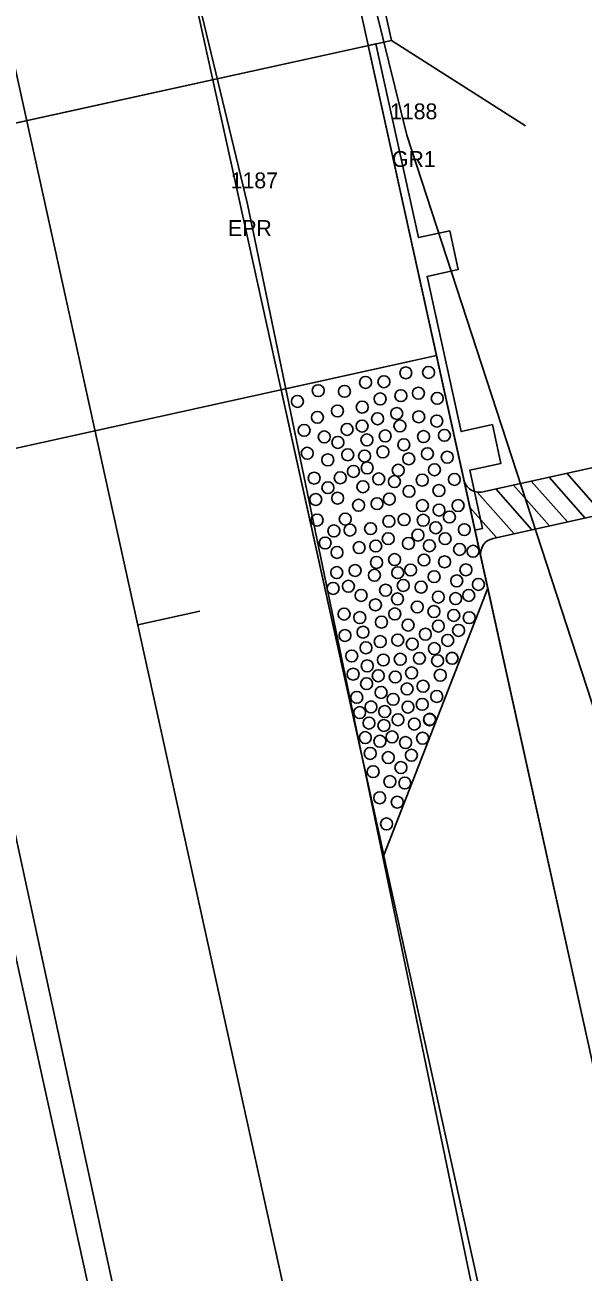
# Model space of a CAD drawing. Extents: x 2520975 to 2526538, y 881018 to 888064.
# Drawn here: x 2523803.6 to 2523838.7, y 884983.7 to 885062.2 of the extents above; entities that cross this region are included whole.
import ezdxf

# ---------------------------------------------------------------- set-up
doc = ezdxf.new("R2010")
doc.units = 0
for name, color, linetype in [('RD_EX_GuardRail', 7, 'Continuous'), ('RD_EX_GuardRail_txCode', 7, 'Continuous'), ('RD_EX_Road', 7, 'Continuous'), ('RD_EX_Road_txCode', 7, 'Continuous'), ('RD_HC_Cl', 7, 'Continuous'), ('RD_HC_Data_Tic', 7, 'Continuous'), ('RD_PD_Bridge', 7, 'Continuous'), ('RD_PD_Final_TrvlWay', 7, 'Continuous'), ('RD_PD_GR', 7, 'Continuous'), ('RD_PD_PaveShd', 7, 'Continuous'), ('RD_SMD_Locator', 7, 'Continuous')]:
    doc.layers.add(name, color=color, linetype=linetype)

# ---------------------------------------------------------------- blocks, each defined once
blk = doc.blocks.new('TBC1')
at = {"layer": 'RD_PD_GR'}
blk.add_lwpolyline([(12.5, 2.5), (15, 2.5), (15, 0.492), (25, 0.492), (25, 2.5), (27.5, 2.5), (27.5, 0.492), (31.25, 0.492), (31.25, 0), (0, 0), (0, 0.492), (12.5, 0.492)], close=True, dxfattribs=at)

msp = doc.modelspace()

# ---------------------------------------------------------------- linework, layer by layer
at = {"layer": 'RD_EX_GuardRail'}
msp.add_lwpolyline([(2523841.112, 885013.814), (2523827.604, 885055.265), (2523819.275, 885089.086)], dxfattribs=at)
at = {"layer": 'RD_EX_Road'}
for p, q in [((2523817.578, 885050.917), (2523809.375, 885084.881)), ((2523837.97, 884952.456), (2523817.578, 885050.917)), ((2523816.996, 884946.299), (2523795.465, 885045.906))]:
    msp.add_line(p, q, dxfattribs=at)
at = {"layer": 'RD_HC_Cl'}
for p, q in [((2523662.651, 885798.932), (2524219.244, 883271.288)), ((2523641.165, 885794.201), (2524197.759, 883266.557))]:
    msp.add_line(p, q, dxfattribs=at)
at = {"layer": 'RD_HC_Data_Tic'}
msp.add_line((2523810.669, 885024.44), (2523814.575, 885025.3), dxfattribs=at)
at = {"layer": 'RD_PD_Bridge'}
for p, q in [((2523780.729, 885051.128), (2523826.629, 885061.235)), ((2523826.629, 885061.235), (2523835.056, 885055.85)), ((2523825.164, 885060.913), (2523829.465, 885041.381)), ((2523829.465, 885041.381), (2523786.495, 885031.918))]:
    msp.add_line(p, q, dxfattribs=at)
for points in [[(2523826.629, 885061.235), (2523798.673, 885188.194)], [(2523780.729, 885051.128), (2523826.629, 885061.235)]]:
    msp.add_lwpolyline(points, dxfattribs=at)
at = {"layer": 'RD_PD_Final_TrvlWay'}
for p, q in [((2523720.239, 885490.907), (2524037.438, 884050.417)), ((2523696.801, 885485.745), (2524014, 884045.256))]:
    msp.add_line(p, q, dxfattribs=at)
at = {"layer": 'RD_PD_GR'}
msp.add_line((2523831.885, 885030.394), (2523990.484, 884310.149), dxfattribs=at)
at = {"layer": 'RD_PD_PaveShd'}
for p, q in [((2523819.699, 885039.23), (2523829.465, 885041.381)), ((2523829.465, 885041.381), (2523831.401, 885032.591)), ((2523819.699, 885039.23), (2523826.151, 885009.932)), ((2523854.955, 885037.791), (2523832.378, 885032.807)), ((2523833.022, 885029.877), (2523855.634, 885034.868)), ((2523836.542, 885033.726), (2523838.816, 885031.156)), ((2523837.659, 885033.973), (2523839.933, 885031.402)), ((2523837.659, 885033.973), (2523839.933, 885031.402)), ((2523833.191, 885032.986), (2523835.465, 885030.416)), ((2523833.191, 885032.986), (2523835.465, 885030.416)), ((2523834.308, 885033.233), (2523836.582, 885030.663)), ((2523834.308, 885033.233), (2523836.582, 885030.663)), ((2523835.425, 885033.48), (2523837.699, 885030.909)), ((2523835.425, 885033.48), (2523837.699, 885030.909)), ((2523831.401, 885032.591), (2523832.046, 885029.661)), ((2523832.027, 885032.793), (2523834.348, 885030.17)), ((2523831.577, 885031.792), (2523833.231, 885029.923)), ((2523832.046, 885029.661), (2523832.691, 885026.732)), ((2523826.151, 885009.932), (2523832.691, 885026.732))]:
    msp.add_line(p, q, dxfattribs=at)
for centre in [(2523824.999, 885039.698), (2523824.999, 885039.698), (2523826.153, 885039.739), (2523826.153, 885039.739), (2523827.534, 885040.3), (2523827.534, 885040.3), (2523828.967, 885040.325), (2523828.967, 885040.325), (2523828.967, 885040.325), (2523822.02, 885039.178), (2523822.02, 885039.178), (2523823.673, 885039.133), (2523823.673, 885039.133), (2523827.222, 885038.86), (2523827.222, 885038.86), (2523828.326, 885039.017), (2523828.326, 885039.017), (2523820.715, 885038.501), (2523820.715, 885038.501), (2523824.791, 885038.139), (2523824.791, 885038.139), (2523825.918, 885038.659), (2523825.918, 885038.659), (2523829.513, 885038.692), (2523829.513, 885038.692), (2523821.973, 885037.498), (2523821.973, 885037.498), (2523823.233, 885037.898), (2523823.233, 885037.898), (2523825.757, 885037.407), (2523825.757, 885037.407), (2523826.962, 885037.739), (2523826.962, 885037.739), (2523828.347, 885037.529), (2523828.347, 885037.529), (2523829.482, 885037.263), (2523829.482, 885037.263), (2523821.137, 885036.679), (2523821.137, 885036.679), (2523823.836, 885036.738), (2523823.836, 885036.738), (2523824.78, 885036.947), (2523824.78, 885036.947), (2523827.161, 885036.956), (2523827.161, 885036.956), (2523822.403, 885036.265), (2523822.403, 885036.265), (2523823.257, 885035.918), (2523823.257, 885035.918), (2523825.086, 885036.073), (2523825.086, 885036.073), (2523826.234, 885036.326), (2523826.234, 885036.326), (2523827.408, 885035.773), (2523827.408, 885035.773), (2523828.647, 885036.286), (2523828.647, 885036.286), (2523829.96, 885036.364), (2523829.96, 885036.364), (2523821.33, 885035.236), (2523821.33, 885035.236), (2523823.878, 885035.137), (2523823.878, 885035.137), (2523824.938, 885035.058), (2523826.089, 885035.32), (2523826.089, 885035.32), (2523827.719, 885034.884), (2523827.719, 885034.884), (2523828.889, 885035.205), (2523828.889, 885035.205), (2523830.139, 885034.988), (2523830.139, 885034.988), (2523822.624, 885034.82), (2523822.624, 885034.82), (2523824.24, 885034.09), (2523824.24, 885034.09), (2523825.101, 885034.315), (2523825.101, 885034.315), (2523827.057, 885034.167), (2523827.057, 885034.167), (2523829.333, 885034.196), (2523829.333, 885034.196), (2523821.767, 885033.666), (2523821.767, 885033.666), (2523823.407, 885033.689), (2523823.407, 885033.689), (2523825.83, 885033.62), (2523825.83, 885033.62), (2523826.817, 885033.452), (2523826.817, 885033.452), (2523828.563, 885033.542), (2523828.563, 885033.542), (2523830.587, 885033.586), (2523830.587, 885033.586), (2523822.633, 885033.066), (2523822.633, 885033.066), (2523824.832, 885033.125), (2523824.832, 885033.125), (2523827.734, 885032.835), (2523827.734, 885032.835), (2523829.618, 885032.888), (2523829.618, 885032.888), (2523821.864, 885032.324), (2523821.864, 885032.324), (2523823.244, 885032.408), (2523823.244, 885032.408), (2523824.564, 885031.963), (2523824.564, 885031.963), (2523825.721, 885032.06), (2523825.721, 885032.06), (2523826.497, 885032.349), (2523826.497, 885032.349), (2523828.577, 885031.941), (2523828.577, 885031.941), (2523830.823, 885031.944), (2523830.823, 885031.944), (2523821.953, 885031.028), (2523821.953, 885031.028), (2523823.725, 885031.088), (2523823.725, 885031.088), (2523826.467, 885030.948), (2523826.467, 885030.948), (2523827.428, 885031.058), (2523827.428, 885031.058), (2523828.627, 885031.016), (2523828.627, 885031.016), (2523829.621, 885031.656), (2523829.621, 885031.656), (2523830.274, 885031.22), (2523830.274, 885031.22), (2523823.006, 885030.346), (2523823.006, 885030.346), (2523824.02, 885030.397), (2523824.02, 885030.397), (2523825.316, 885030.486), (2523825.316, 885030.486), (2523829.418, 885030.543), (2523829.418, 885030.543), (2523831.214, 885030.426), (2523831.214, 885030.426), (2523822.459, 885029.586), (2523825.639, 885029.394), (2523825.639, 885029.394), (2523826.429, 885029.856), (2523826.429, 885029.856), (2523827.701, 885029.554), (2523827.701, 885029.554), (2523828.295, 885030.079), (2523828.295, 885030.079), (2523829.019, 885029.41), (2523829.019, 885029.41), (2523830.001, 885029.855), (2523830.001, 885029.855), (2523823.203, 885028.987), (2523823.203, 885028.987), (2523824.598, 885029.295), (2523824.598, 885029.295), (2523830.914, 885029.182), (2523830.914, 885029.182), (2523831.766, 885029.063), (2523831.766, 885029.063), (2523824.341, 885027.852), (2523824.341, 885027.852), (2523825.691, 885028.358), (2523825.691, 885028.358), (2523826.825, 885028.541), (2523826.825, 885028.541), (2523827.831, 885027.884), (2523827.831, 885027.884), (2523828.676, 885028.512), (2523828.676, 885028.512), (2523829.968, 885028.398), (2523829.968, 885028.398), (2523831.312, 885027.895), (2523831.312, 885027.895), (2523823.189, 885027.719), (2523823.189, 885027.719), (2523825.558, 885027.553), (2523825.558, 885027.553), (2523827.027, 885027.715), (2523827.027, 885027.715), (2523829.314, 885027.463), (2523829.314, 885027.463), (2523830.736, 885027.201), (2523830.736, 885027.201), (2523832.098, 885026.977), (2523832.098, 885026.977), (2523832.098, 885026.977), (2523822.96, 885026.723), (2523822.96, 885026.723), (2523823.922, 885026.86), (2523823.922, 885026.86), (2523824.722, 885026.285), (2523824.722, 885026.285), (2523826.258, 885026.612), (2523826.258, 885026.612), (2523827.371, 885026.909), (2523827.371, 885026.909), (2523828.495, 885026.805), (2523828.495, 885026.805), (2523831.494, 885026.285), (2523831.494, 885026.285), (2523825.619, 885025.69), (2523825.619, 885025.69), (2523827.01, 885026.061), (2523827.01, 885026.061), (2523828.25, 885025.557), (2523828.25, 885025.557), (2523829.579, 885026.177), (2523829.579, 885026.177), (2523830.668, 885026.083), (2523830.668, 885026.083), (2523823.647, 885025.109), (2523823.647, 885025.109), (2523824.637, 885024.887), (2523824.637, 885024.887), (2523826.84, 885025.117), (2523826.84, 885025.117), (2523829.299, 885025.269), (2523829.299, 885025.269), (2523830.547, 885025.024), (2523830.547, 885025.024), (2523831.521, 885024.88), (2523831.521, 885024.88), (2523824.84, 885023.97), (2523824.84, 885023.97), (2523826.002, 885024.601), (2523826.002, 885024.601), (2523827.675, 885024.414), (2523827.675, 885024.414), (2523828.762, 885023.842), (2523828.762, 885023.842), (2523829.58, 885024.354), (2523829.58, 885024.354), (2523830.854, 885024.079), (2523830.854, 885024.079), (2523823.705, 885023.759), (2523823.705, 885023.759), (2523825.92, 885023.378), (2523825.92, 885023.378), (2523827.027, 885023.472), (2523827.027, 885023.472), (2523827.938, 885023.219), (2523827.938, 885023.219), (2523830.17, 885023.448), (2523830.17, 885023.448), (2523824.131, 885022.47), (2523824.131, 885022.47), (2523825.026, 885022.984), (2523825.026, 885022.984), (2523827.181, 885022.266), (2523827.181, 885022.266), (2523828.389, 885022.322), (2523828.389, 885022.322), (2523829.325, 885022.938), (2523829.325, 885022.938), (2523830.44, 885022.322), (2523830.449, 885022.329), (2523825.102, 885021.848), (2523825.102, 885021.848), (2523826.119, 885022.219), (2523826.119, 885022.219), (2523829.53, 885022.168), (2523829.53, 885022.168), (2523824.22, 885021.325), (2523824.22, 885021.325), (2523825.063, 885020.725), (2523825.063, 885020.725), (2523825.799, 885021.225), (2523825.799, 885021.225), (2523826.869, 885021.144), (2523826.869, 885021.144), (2523827.898, 885021.404), (2523827.898, 885021.404), (2523829.699, 885021.26), (2523829.699, 885021.26), (2523825.975, 885020.172), (2523825.975, 885020.172), (2523827.612, 885020.396), (2523827.612, 885020.396), (2523828.618, 885020.568), (2523828.618, 885020.568), (2523829.483, 885019.92), (2523829.483, 885019.92), (2523824.449, 885019.865), (2523824.449, 885019.865), (2523825.343, 885019.265), (2523825.343, 885019.265), (2523826.735, 885019.741), (2523826.735, 885019.741), (2523827.668, 885019.251), (2523827.668, 885019.251), (2523828.563, 885019.424), (2523828.563, 885019.424), (2523824.631, 885018.908), (2523824.631, 885018.908), (2523826.207, 885018.972), (2523826.207, 885018.972), (2523827.041, 885018.456), (2523827.041, 885018.456), (2523829.025, 885018.456), (2523829.036, 885018.488), (2523825.216, 885018.247), (2523825.216, 885018.247), (2523826.153, 885018.093), (2523826.153, 885018.093), (2523828.067, 885018.184), (2523828.067, 885018.184), (2523824.984, 885017.331), (2523824.984, 885017.331), (2523825.9, 885017.099), (2523825.9, 885017.099), (2523826.67, 885017.372), (2523826.67, 885017.372), (2523827.515, 885017.016), (2523827.515, 885017.016), (2523828.589, 885017.293), (2523828.589, 885017.293), (2523825.292, 885016.334), (2523825.292, 885016.334), (2523826.43, 885016.072), (2523826.43, 885016.072), (2523827.885, 885016.22), (2523827.226, 885015.446), (2523827.226, 885015.446), (2523825.478, 885015.184), (2523825.478, 885015.184), (2523826.53, 885014.559), (2523826.53, 885014.559), (2523827.471, 885014.469), (2523827.471, 885014.469), (2523825.89, 885013.54), (2523825.89, 885013.54), (2523826.996, 885013.264), (2523826.996, 885013.264), (2523826.319, 885011.894)]:
    msp.add_circle(centre, 0.375, dxfattribs=at)
for centre, start, end in [((2523832.162, 885033.783), 192.41848, 282.4481), ((2523833.238, 885028.9), 102.4481, 192.41848)]:
    msp.add_arc(centre, 1, start, end, dxfattribs=at)
at = {"layer": 'RD_SMD_Locator'}
for centre in [(2523827.604, 885055.265), (2523817.578, 885050.917)]:
    msp.add_circle(centre, 0.001, dxfattribs=at)

# ---------------------------------------------------------------- block references
at = {"layer": 'RD_PD_Bridge', "rotation": -77.58151740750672}
msp.add_blockref('TBC1', (2523825.164, 885060.913), dxfattribs=at)

# ---------------------------------------------------------------- texts
at = {"layer": 'RD_EX_GuardRail_txCode'}
for s, p in [('1188', (2523826.541, 885056.265)), ('GR1', (2523826.659, 885053.265))]:
    msp.add_text(s, height=1, dxfattribs=at).set_placement(p)
at = {"layer": 'RD_EX_Road_txCode'}
for s, p in [('1187', (2523816.515, 885051.917)), ('EPR', (2523816.35, 885048.917))]:
    msp.add_text(s, height=1, dxfattribs=at).set_placement(p)

doc.saveas('drawing.dxf')
